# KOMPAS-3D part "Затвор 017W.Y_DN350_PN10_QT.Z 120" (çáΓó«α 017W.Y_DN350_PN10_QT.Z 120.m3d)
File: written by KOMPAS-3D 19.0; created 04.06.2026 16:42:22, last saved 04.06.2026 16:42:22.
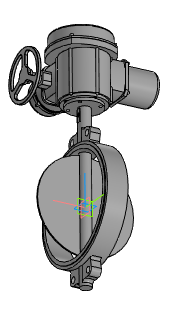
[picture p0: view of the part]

Document properties: Автор: Энергия; Полное имя файла: ..\..\..\3d для проектировщиков\017W разные\x.x Тип 017W.Y(S) Затвор дисковый поворотный межфланцевый\Затвор 017W.Y(S)_DN32-DN450_QT.Z\Затвор 017W.Y_DN350_PN10_QT.Z 120.a3d

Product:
- Part/product: Затвор 017W.Y_DN350_PN10_QT.Z 120
    Масса: 99.3798

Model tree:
1. Операция без истории:1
